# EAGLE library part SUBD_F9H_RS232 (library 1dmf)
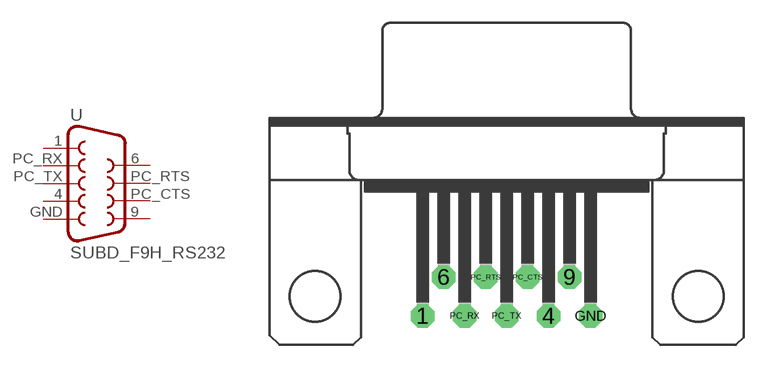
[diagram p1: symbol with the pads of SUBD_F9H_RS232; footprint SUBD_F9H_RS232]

Designator prefix -

## SUBD_F9H_RS232  [SUBD_F9H_RS232]
1  1  pas
4  4  pas
6  6  pas
9  9  pas
GND  GND  pas
PC_CTS  8  pas
PC_RTS  7  pas
PC_RX  PC_RX  pas
PC_TX  PC_TX  pas

## Footprint SUBD_F9H_RS232 (pad centres in mm)
drill 1.016 octagon: 1 -5.486,-7.62; 4 2.743,-7.62; 6 -4.115,-5.08; 9 4.115,-5.08; GND 5.486,-7.62; PC_CTS 1.372,-5.08; PC_RTS -1.372,-5.08; PC_RX -2.743,-7.62; PC_TX 0,-7.62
